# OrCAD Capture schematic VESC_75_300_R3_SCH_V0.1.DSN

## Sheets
1 01_Overview
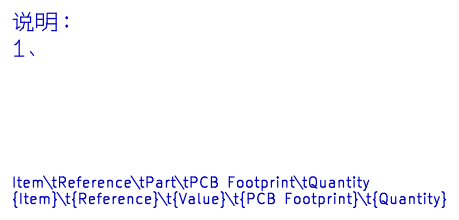
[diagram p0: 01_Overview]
2 02_Vresion
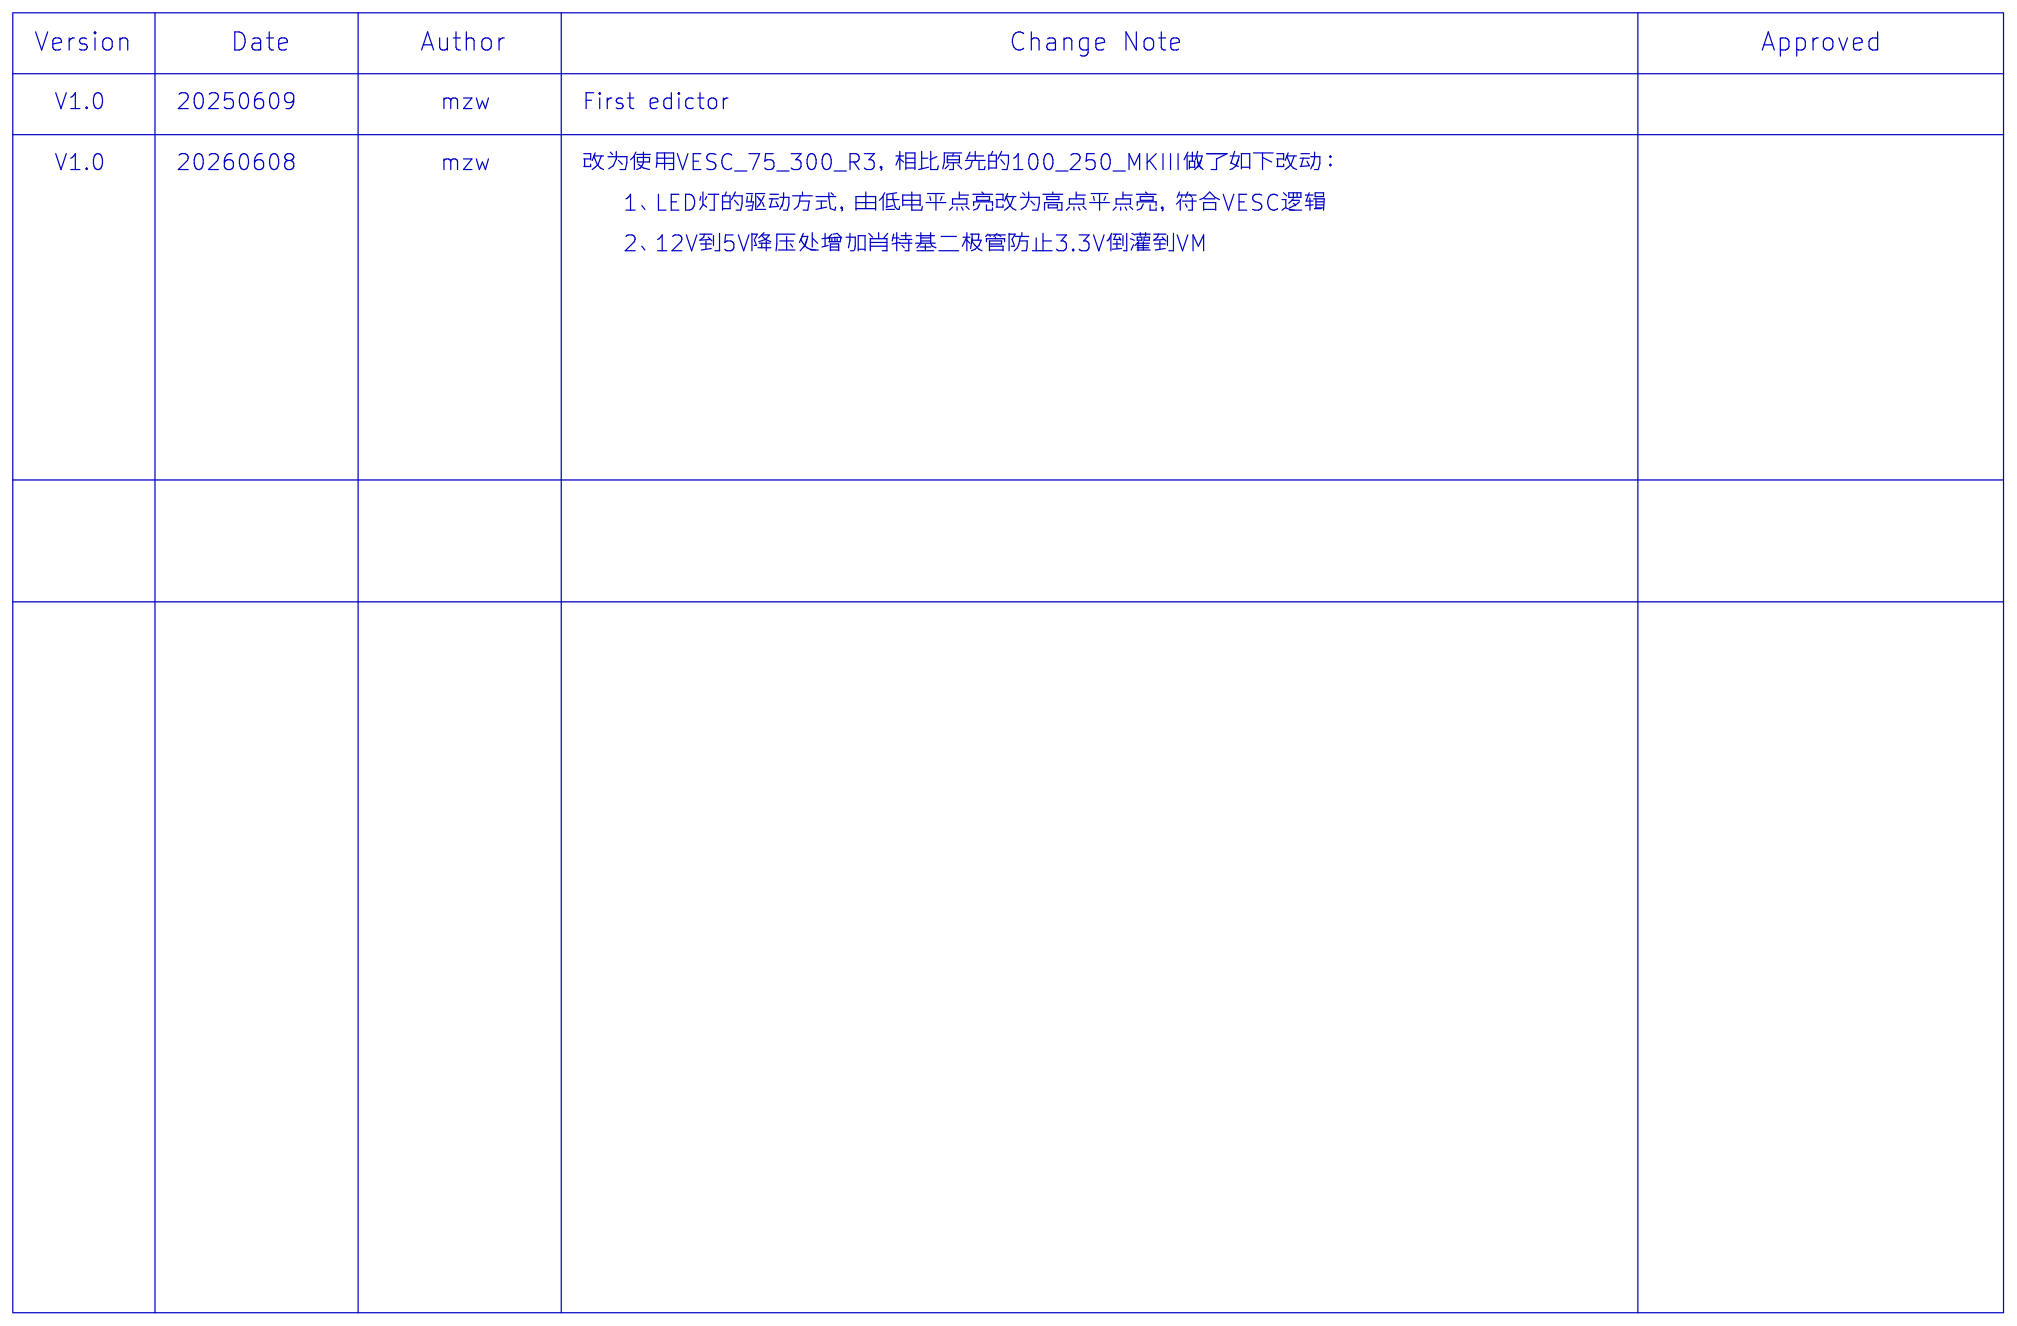
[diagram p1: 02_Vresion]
3 03_CAN: size A3
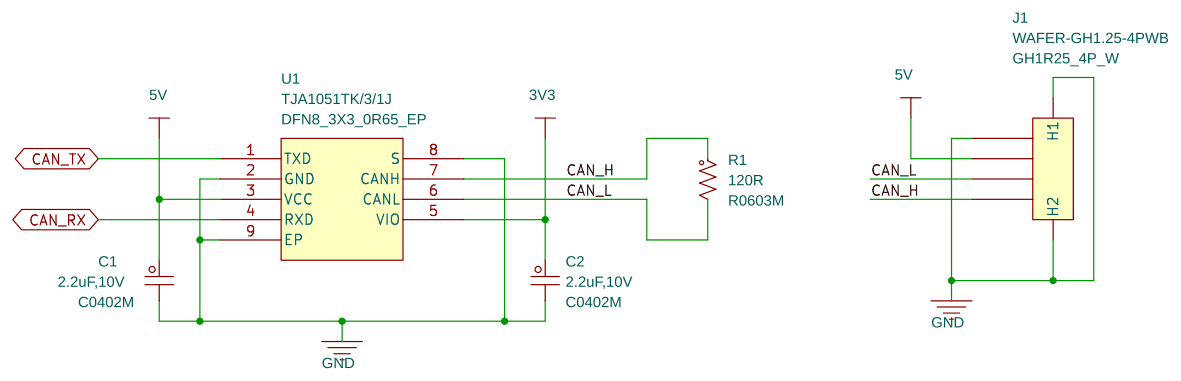
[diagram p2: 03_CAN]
4 04_MCU: size A3
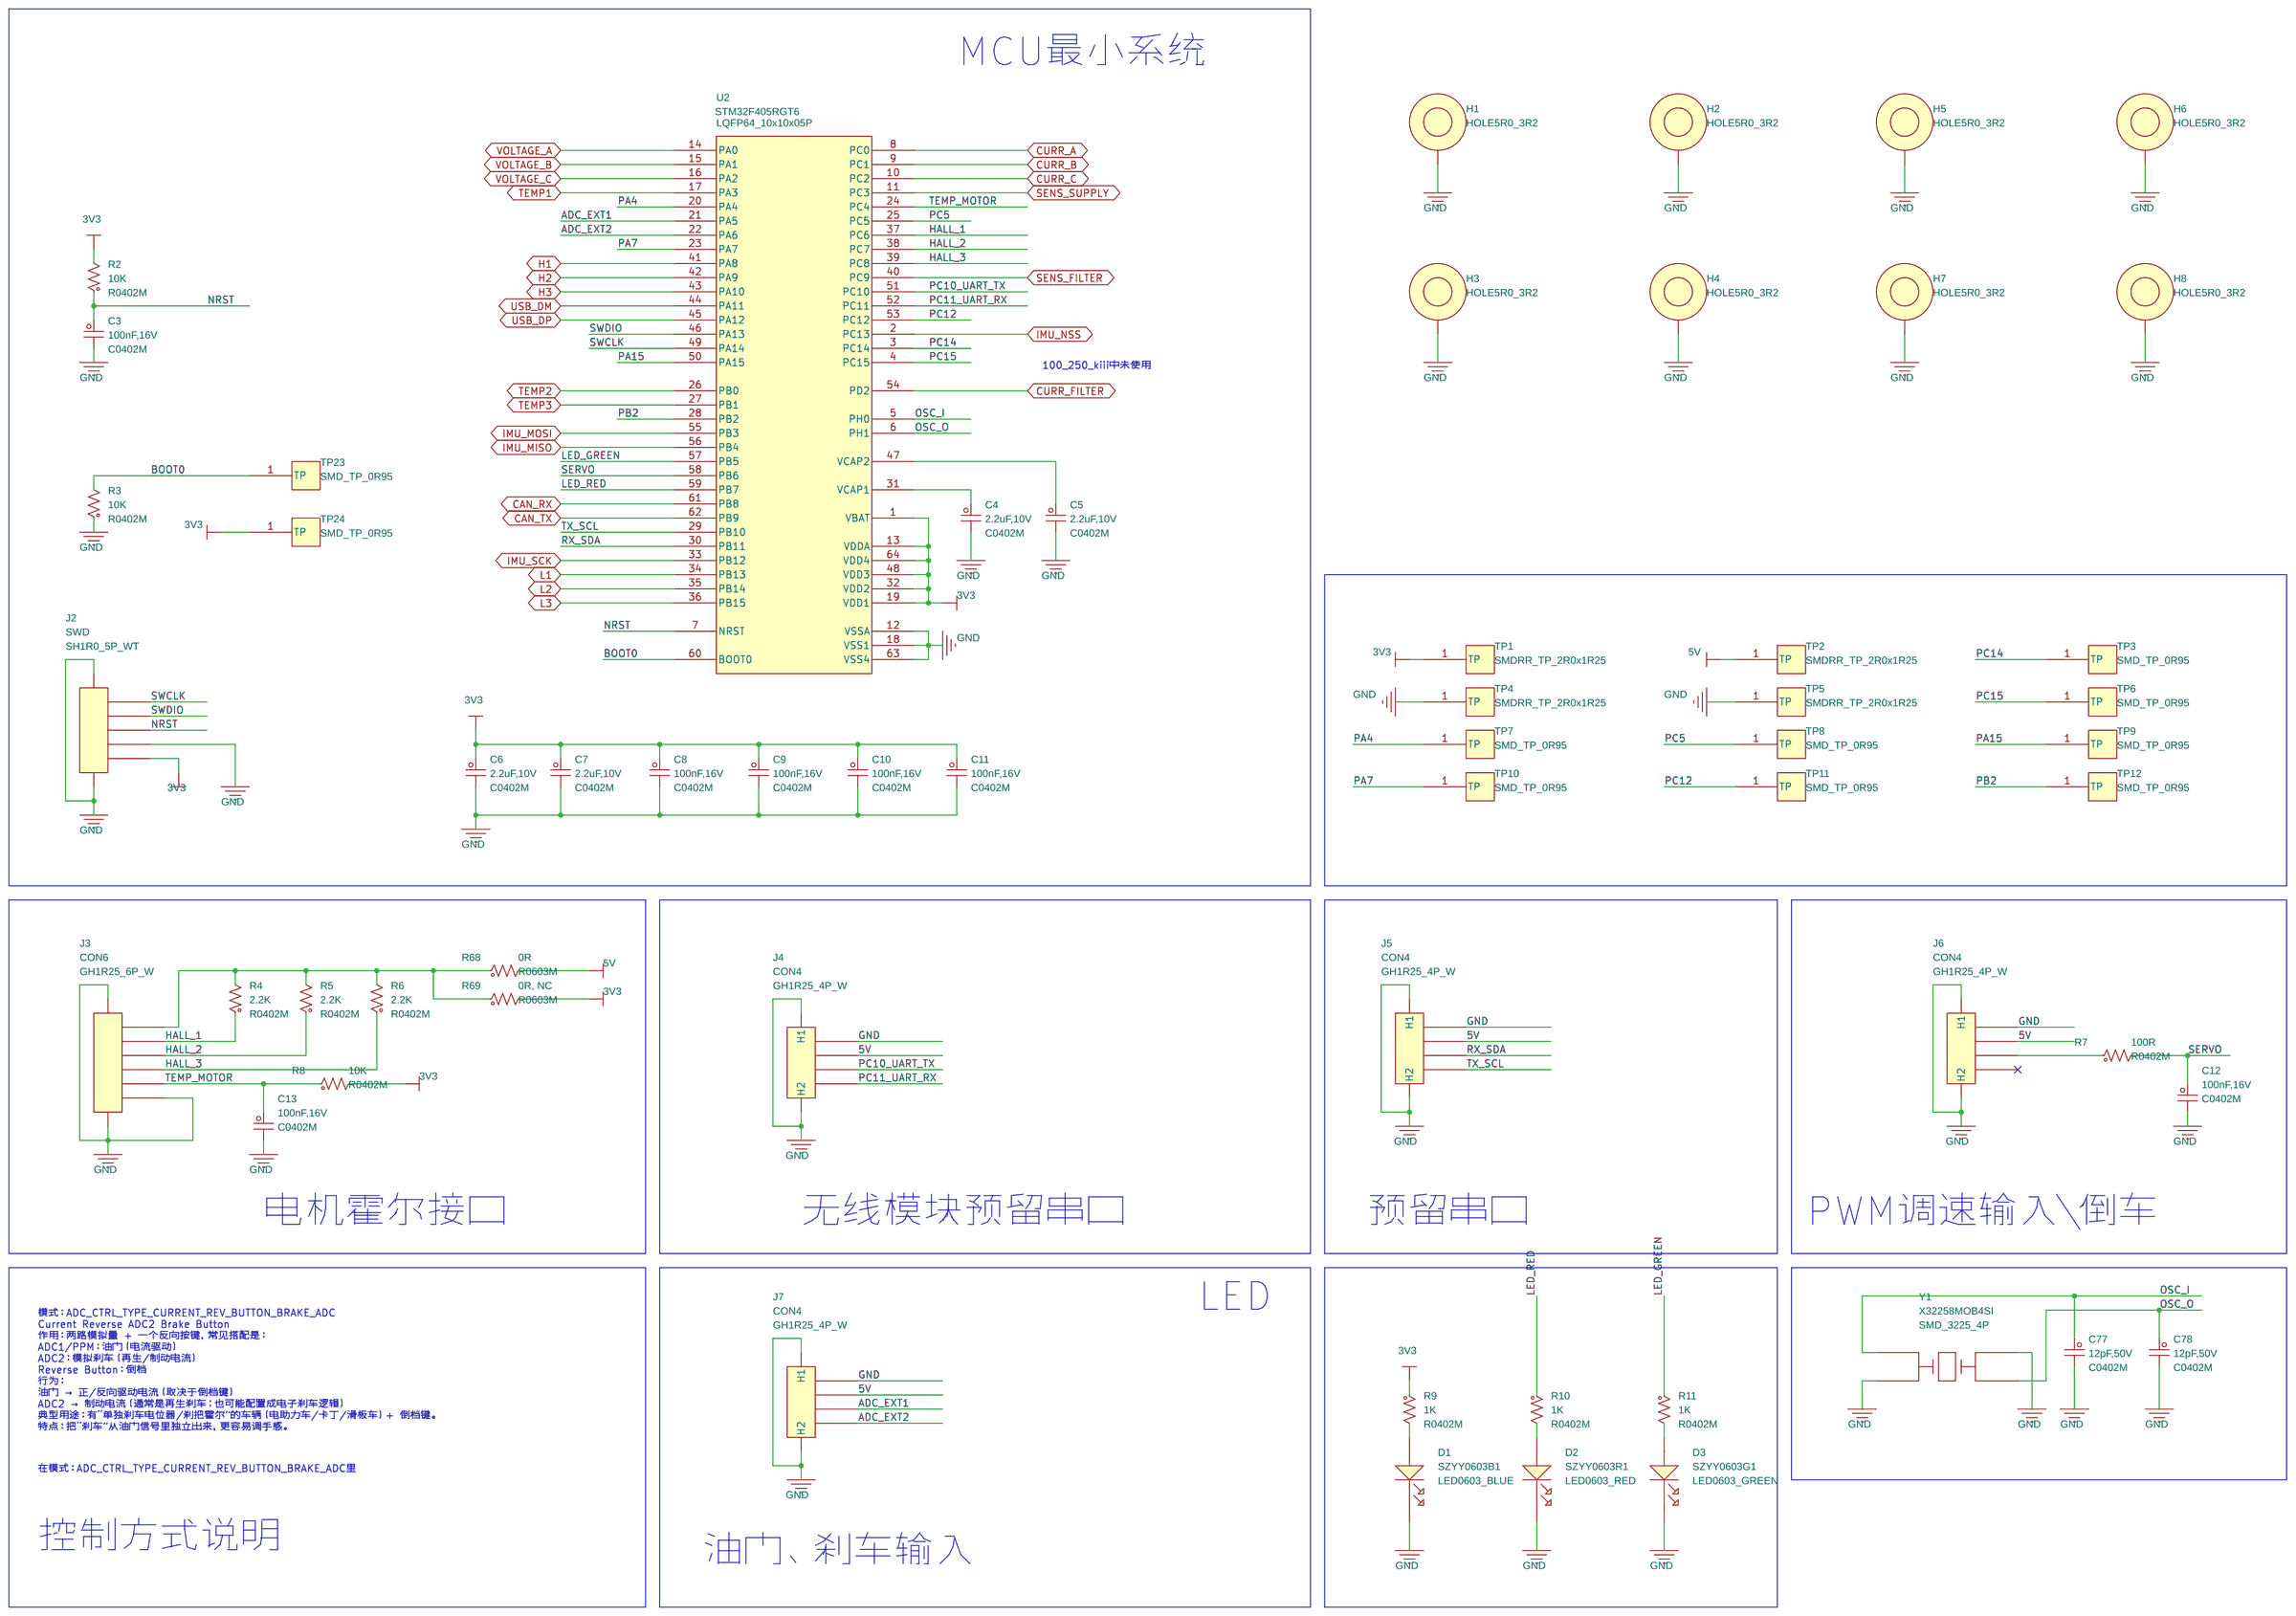
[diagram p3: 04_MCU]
5 05_Sensor: size A3
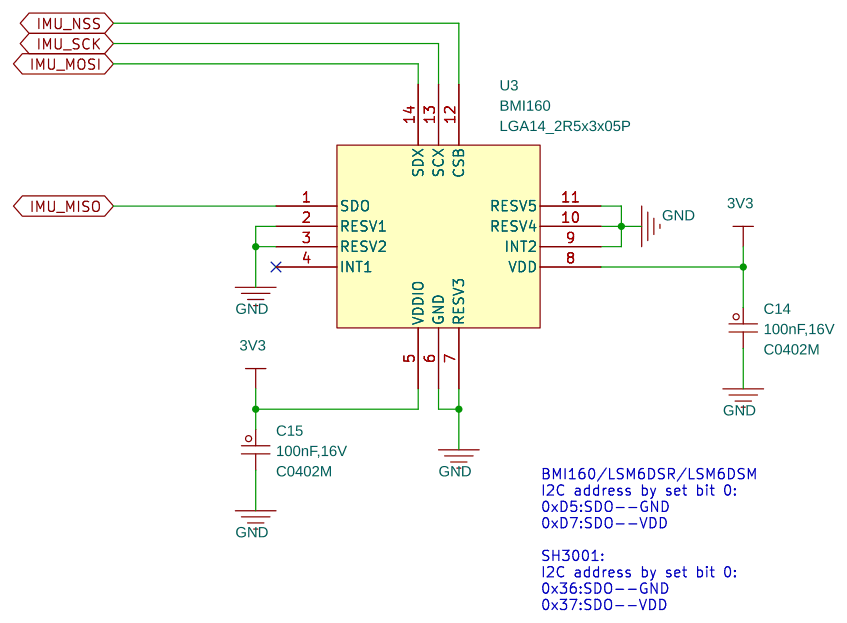
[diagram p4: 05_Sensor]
6 06_USB: size A3
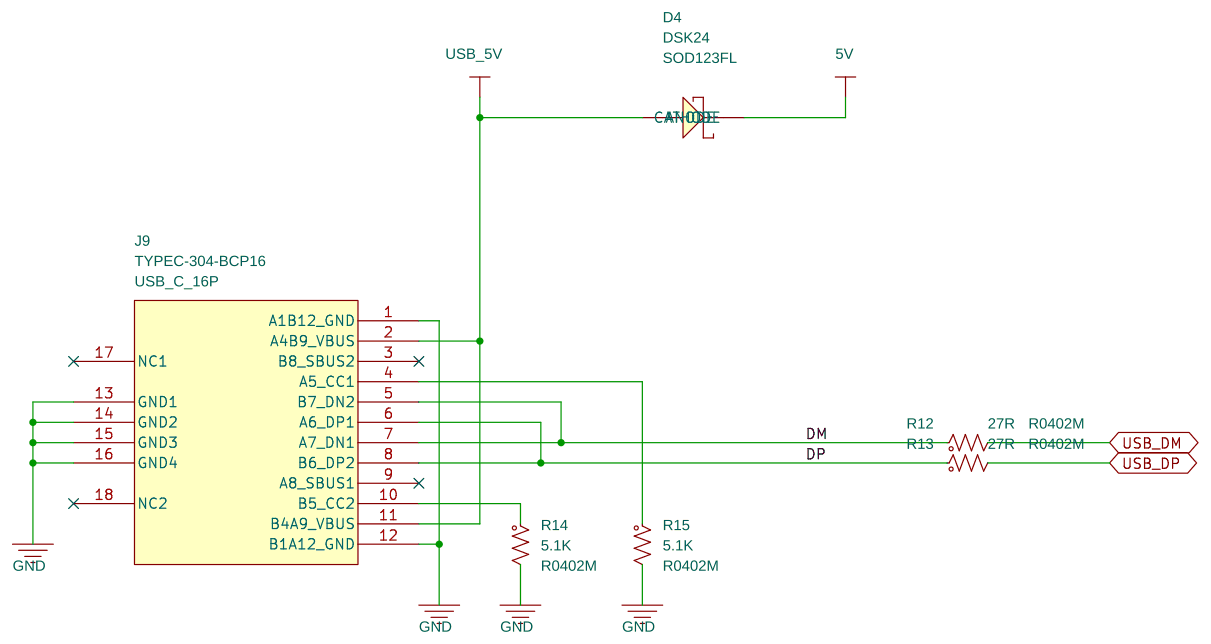
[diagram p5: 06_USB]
7 07_Power: size A3
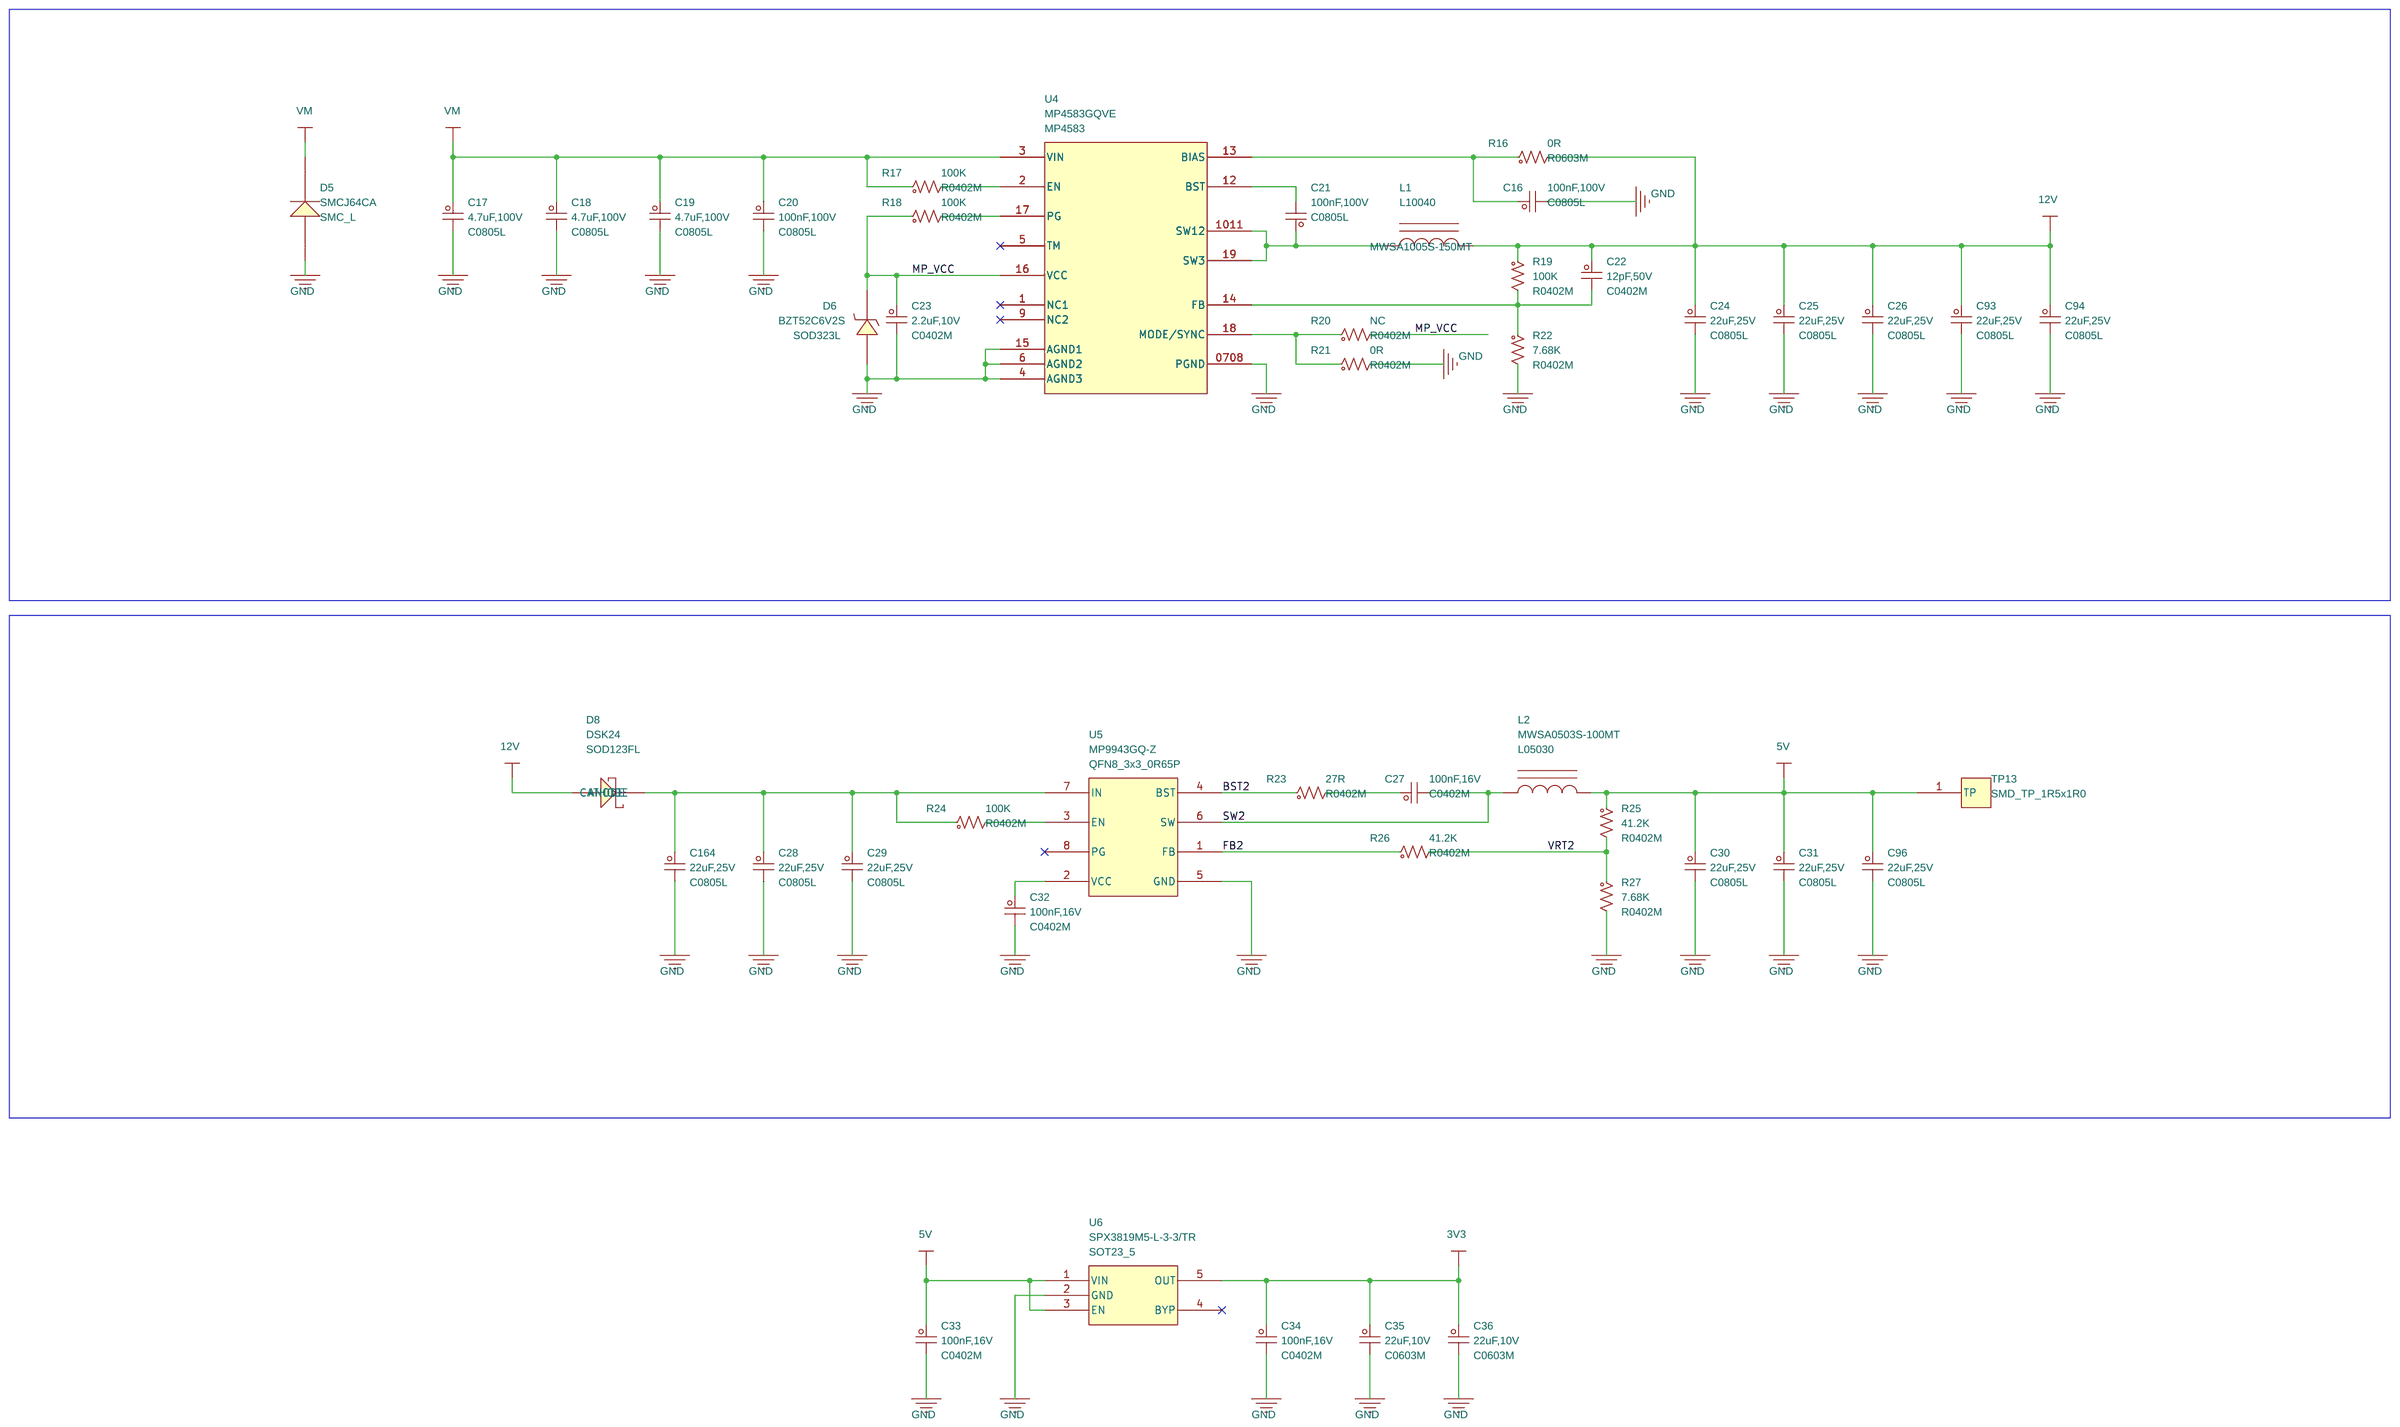
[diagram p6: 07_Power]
8 08_Motor: size A3
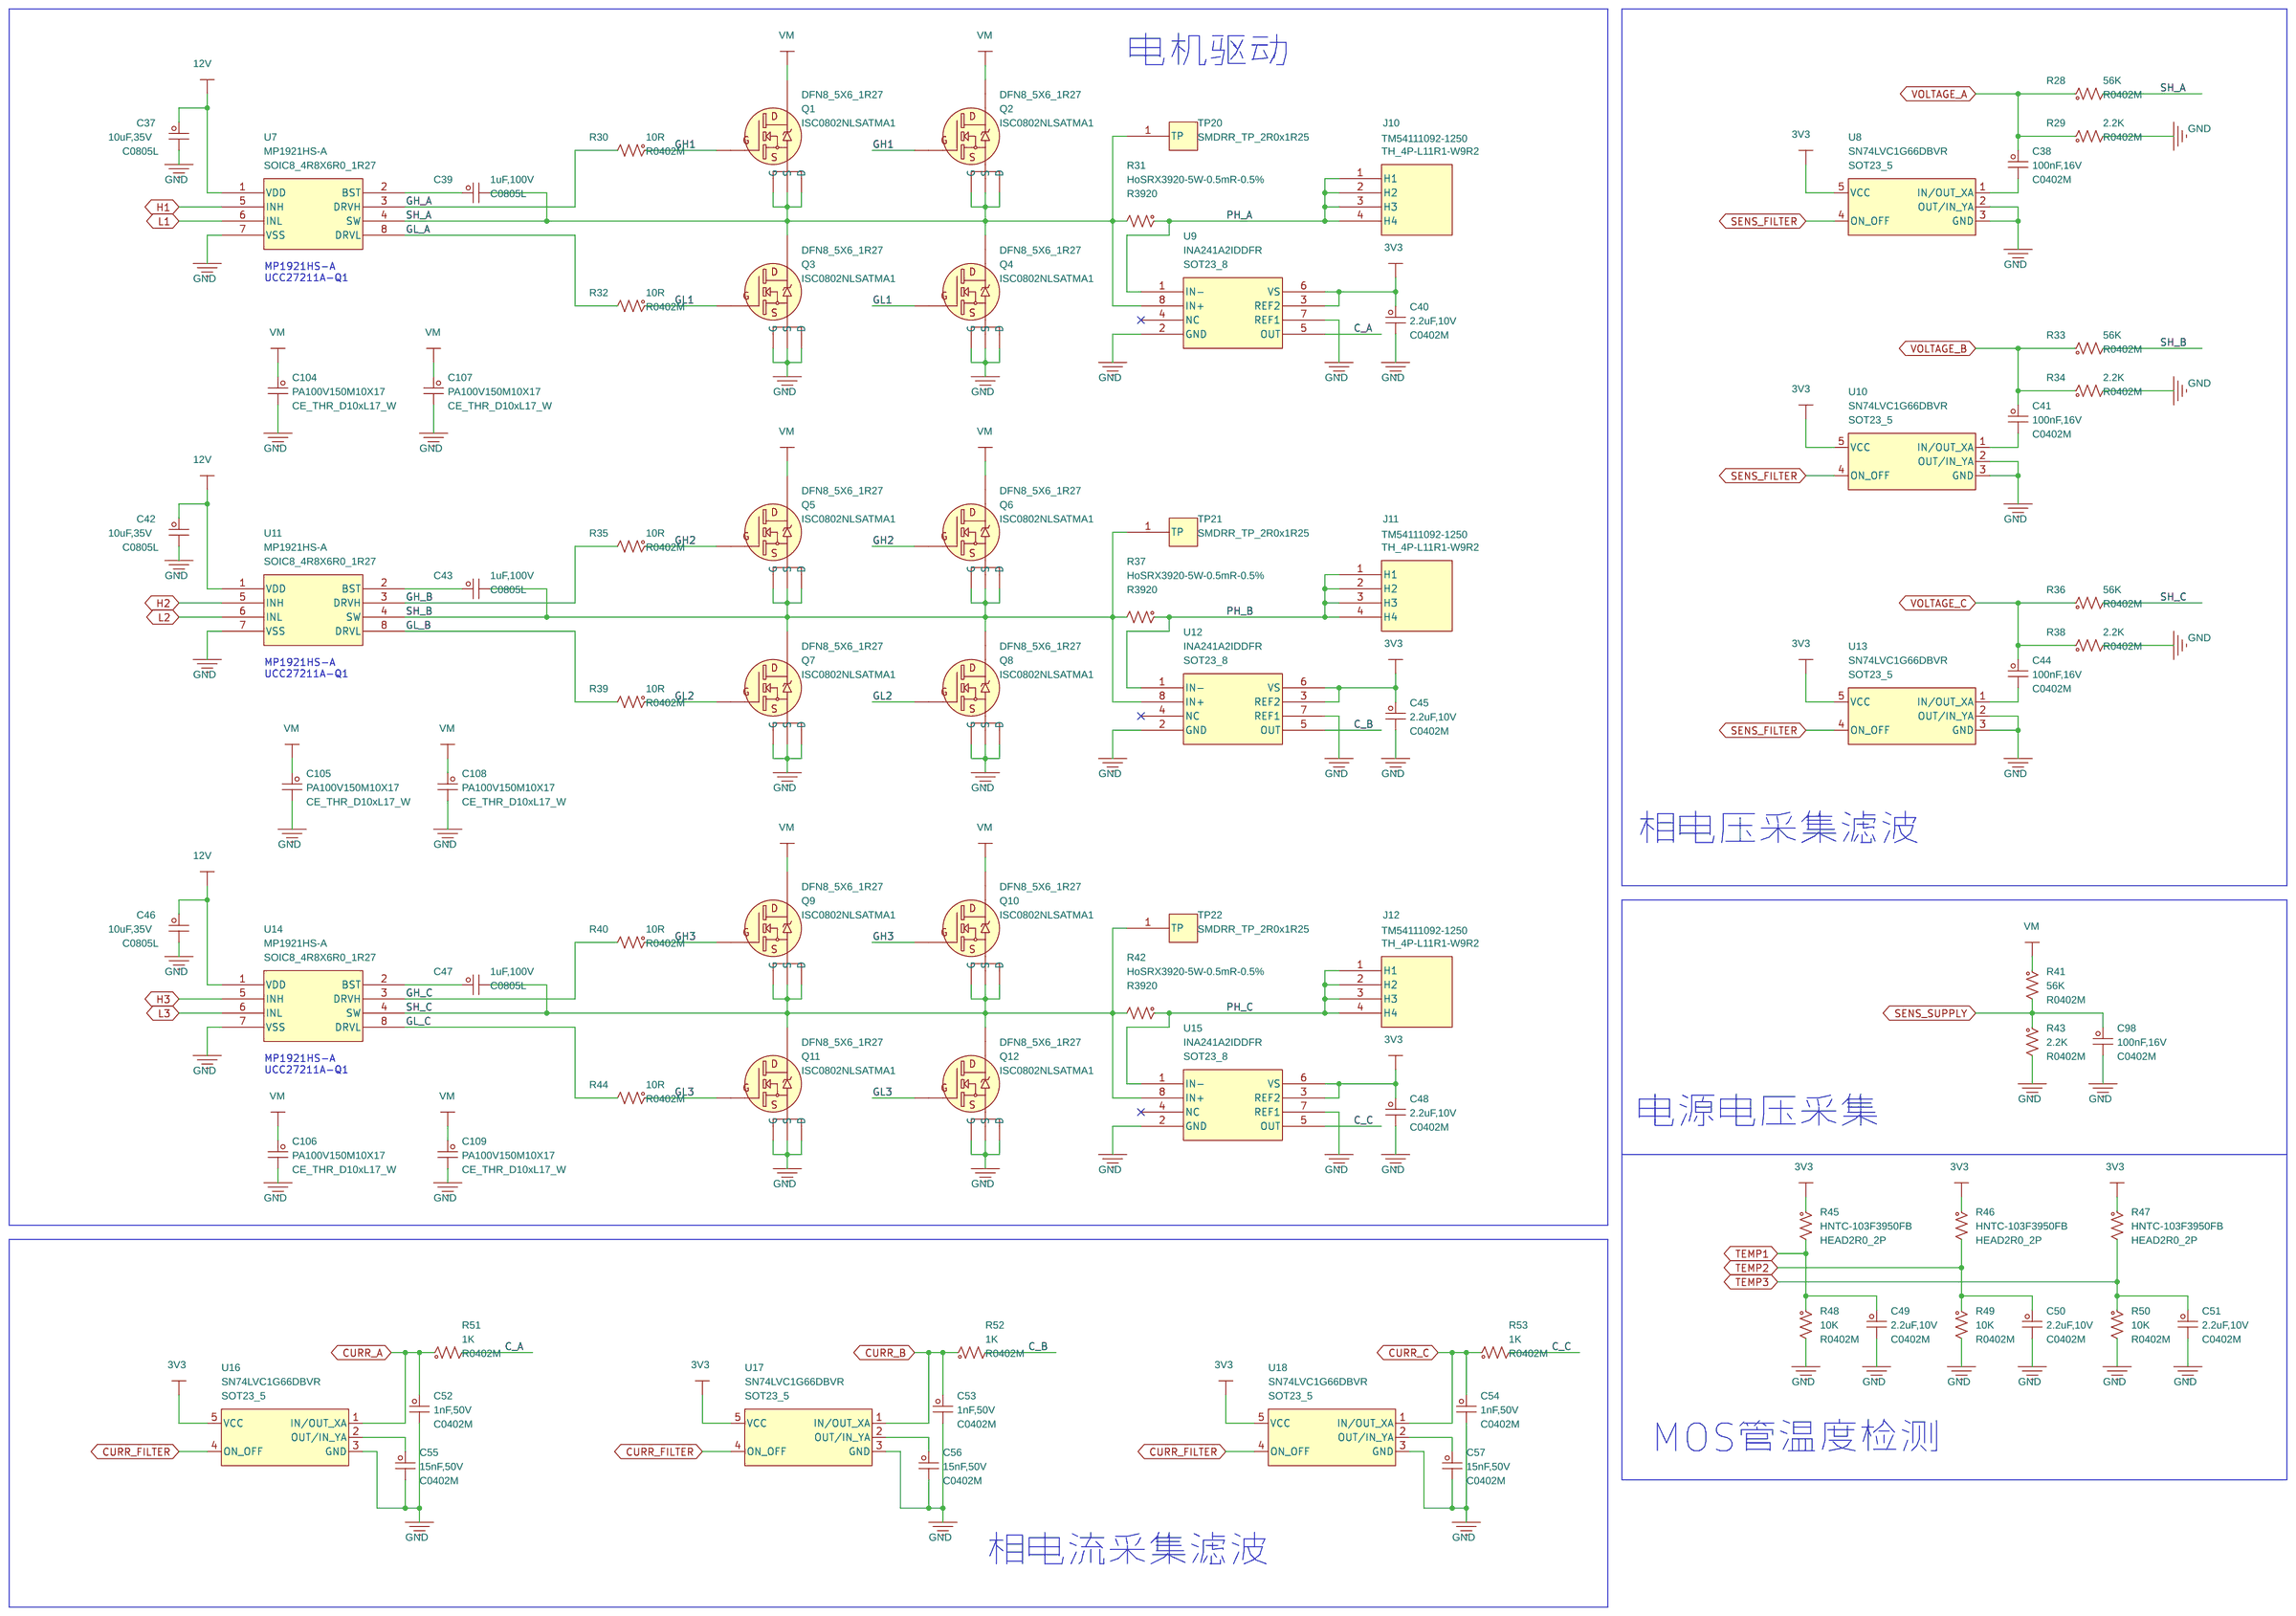
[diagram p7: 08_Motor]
9 09_eFuse: size A3
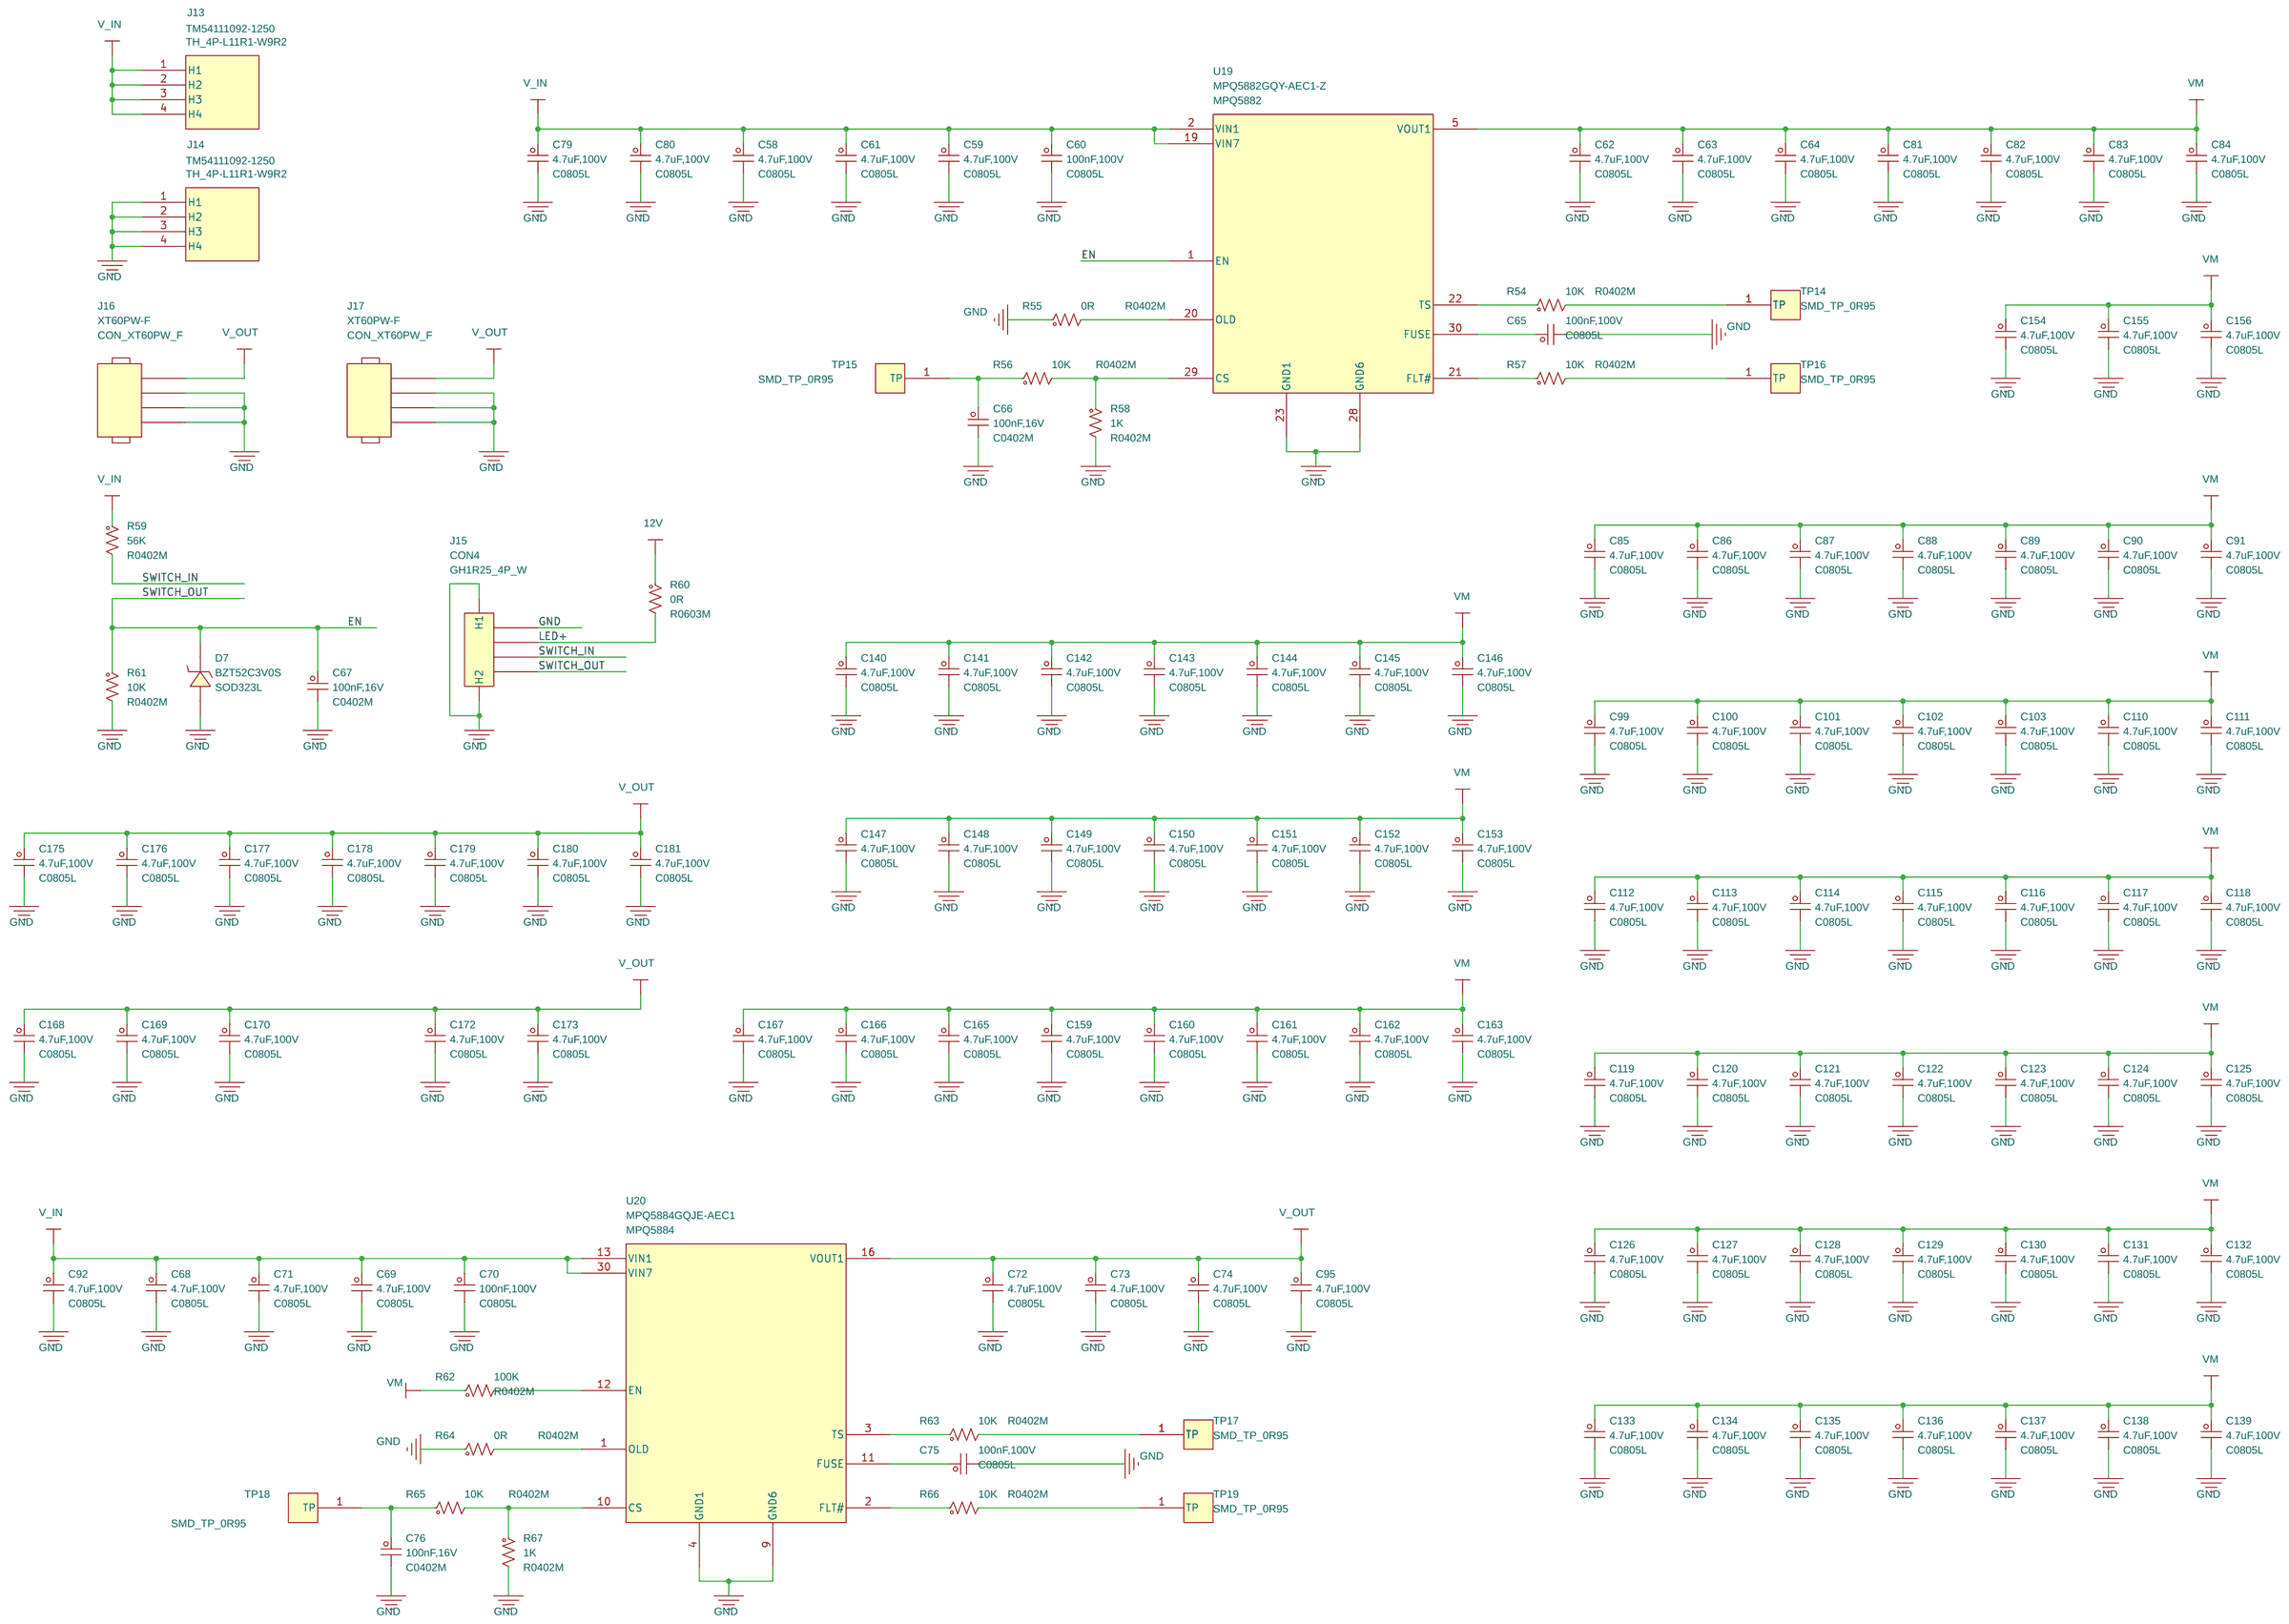
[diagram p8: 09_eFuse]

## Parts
sheet 03_CAN
C1  2.2uF,10V  [C0402M]
C2  2.2uF,10V  [C0402M]
J1  WAFER-GH1.25-4PWB  [GH1R25_4P_W]
R1  120R  [R0603M]
U1  TJA1051TK/3/1J  [DFN8_3X3_0R65_EP]
sheet 04_MCU
C3  100nF,16V  [C0402M]
C4  2.2uF,10V  [C0402M]
C5  2.2uF,10V  [C0402M]
C6  2.2uF,10V  [C0402M]
C7  2.2uF,10V  [C0402M]
C8  100nF,16V  [C0402M]
C9  100nF,16V  [C0402M]
C10  100nF,16V  [C0402M]
C11  100nF,16V  [C0402M]
C12  100nF,16V  [C0402M]
C13  100nF,16V  [C0402M]
C77  12pF,50V  [C0402M]
C78  12pF,50V  [C0402M]
D1  SZYY0603B1  [LED0603_BLUE]
D2  SZYY0603R1  [LED0603_RED]
D3  SZYY0603G1  [LED0603_GREEN]
H1  HOLE  [HOLE5R0_3R2]
H2  HOLE  [HOLE5R0_3R2]
H3  HOLE  [HOLE5R0_3R2]
H4  HOLE  [HOLE5R0_3R2]
H5  HOLE  [HOLE5R0_3R2]
H6  HOLE  [HOLE5R0_3R2]
H7  HOLE  [HOLE5R0_3R2]
H8  HOLE  [HOLE5R0_3R2]
J2  SWD  [SH1R0_5P_WT]
J3  CON6  [GH1R25_6P_W]
J4  CON4  [GH1R25_4P_W]
J5  CON4  [GH1R25_4P_W]
J6  CON4  [GH1R25_4P_W]
J7  CON4  [GH1R25_4P_W]
R2  10K  [R0402M]
R3  10K  [R0402M]
R4  2.2K  [R0402M]
R5  2.2K  [R0402M]
R6  2.2K  [R0402M]
R7  100R  [R0402M]
R8  10K  [R0402M]
R9  1K  [R0402M]
R10  1K  [R0402M]
R11  1K  [R0402M]
R68  0R  [R0603M]
R69  0R, NC  [R0603M]
TP1  TestPoint  [SMDRR_TP_2R0x1R25]
TP2  TestPoint  [SMDRR_TP_2R0x1R25]
TP3  TestPoint  [SMD_TP_0R95]
TP4  TestPoint  [SMDRR_TP_2R0x1R25]
TP5  TestPoint  [SMDRR_TP_2R0x1R25]
TP6  TestPoint  [SMD_TP_0R95]
TP7  TestPoint  [SMD_TP_0R95]
TP8  TestPoint  [SMD_TP_0R95]
TP9  TestPoint  [SMD_TP_0R95]
TP10  TestPoint  [SMD_TP_0R95]
TP11  TestPoint  [SMD_TP_0R95]
TP12  TestPoint  [SMD_TP_0R95]
TP23  TestPoint  [SMD_TP_0R95]
TP24  TestPoint  [SMD_TP_0R95]
U2  STM32F405RGT6  [LQFP64_10x10x05P]
Y1  X32258MOB4SI  [SMD_3225_4P]
sheet 05_Sensor
C14  100nF,16V  [C0402M]
C15  100nF,16V  [C0402M]
U3  BMI160  [LGA14_2R5x3x05P]
sheet 06_USB
D4  DSK24  [SOD123FL]
J9  TYPEC-304-BCP16  [USB_C_16P]
R12  27R  [R0402M]
R13  27R  [R0402M]
R14  5.1K  [R0402M]
R15  5.1K  [R0402M]
sheet 07_Power
C16  100nF,100V  [C0805L]
C17  4.7uF,100V  [C0805L]
C18  4.7uF,100V  [C0805L]
C19  4.7uF,100V  [C0805L]
C20  100nF,100V  [C0805L]
C21  100nF,100V  [C0805L]
C22  12pF,50V  [C0402M]
C23  2.2uF,10V  [C0402M]
C24  22uF,25V  [C0805L]
C25  22uF,25V  [C0805L]
C26  22uF,25V  [C0805L]
C27  100nF,16V  [C0402M]
C28  22uF,25V  [C0805L]
C29  22uF,25V  [C0805L]
C30  22uF,25V  [C0805L]
C31  22uF,25V  [C0805L]
C32  100nF,16V  [C0402M]
C33  100nF,16V  [C0402M]
C34  100nF,16V  [C0402M]
C35  22uF,10V  [C0603M]
C36  22uF,10V  [C0603M]
C93  22uF,25V  [C0805L]
C94  22uF,25V  [C0805L]
C96  22uF,25V  [C0805L]
C164  22uF,25V  [C0805L]
D5  SMCJ64CA  [SMC_L]
D6  BZT52C6V2S  [SOD323L]
D8  DSK24  [SOD123FL]
L1  MWSA1005S-150MT  [L10040]
L2  MWSA0503S-100MT  [L05030]
R16  0R  [R0603M]
R17  100K  [R0402M]
R18  100K  [R0402M]
R19  100K  [R0402M]
R20  NC  [R0402M]
R21  0R  [R0402M]
R22  7.68K  [R0402M]
R23  27R  [R0402M]
R24  100K  [R0402M]
R25  41.2K  [R0402M]
R26  41.2K  [R0402M]
R27  7.68K  [R0402M]
TP13  TestPoint  [SMD_TP_1R5x1R0]
U4  MP4583GQVE  [MP4583]
U5  MP9943GQ-Z  [QFN8_3x3_0R65P]
U6  SPX3819M5-L-3-3/TR  [SOT23_5]
sheet 08_Motor
C37  10uF,35V  [C0805L]
C38  100nF,16V  [C0402M]
C39  1uF,100V  [C0805L]
C40  2.2uF,10V  [C0402M]
C41  100nF,16V  [C0402M]
C42  10uF,35V  [C0805L]
C43  1uF,100V  [C0805L]
C44  100nF,16V  [C0402M]
C45  2.2uF,10V  [C0402M]
C46  10uF,35V  [C0805L]
C47  1uF,100V  [C0805L]
C48  2.2uF,10V  [C0402M]
C49  2.2uF,10V  [C0402M]
C50  2.2uF,10V  [C0402M]
C51  2.2uF,10V  [C0402M]
C52  1nF,50V  [C0402M]
C53  1nF,50V  [C0402M]
C54  1nF,50V  [C0402M]
C55  15nF,50V  [C0402M]
C56  15nF,50V  [C0402M]
C57  15nF,50V  [C0402M]
C98  100nF,16V  [C0402M]
C104  PA100V150M10X17  [CE_THR_D10xL17_W]
C105  PA100V150M10X17  [CE_THR_D10xL17_W]
C106  PA100V150M10X17  [CE_THR_D10xL17_W]
C107  PA100V150M10X17  [CE_THR_D10xL17_W]
C108  PA100V150M10X17  [CE_THR_D10xL17_W]
C109  PA100V150M10X17  [CE_THR_D10xL17_W]
J10  TM54111092-1250  [TH_4P-L11R1-W9R2]
J11  TM54111092-1250  [TH_4P-L11R1-W9R2]
J12  TM54111092-1250  [TH_4P-L11R1-W9R2]
Q1  ISC0802NLSATMA1  [DFN8_5X6_1R27]
Q2  ISC0802NLSATMA1  [DFN8_5X6_1R27]
Q3  ISC0802NLSATMA1  [DFN8_5X6_1R27]
Q4  ISC0802NLSATMA1  [DFN8_5X6_1R27]
Q5  ISC0802NLSATMA1  [DFN8_5X6_1R27]
Q6  ISC0802NLSATMA1  [DFN8_5X6_1R27]
Q7  ISC0802NLSATMA1  [DFN8_5X6_1R27]
Q8  ISC0802NLSATMA1  [DFN8_5X6_1R27]
Q9  ISC0802NLSATMA1  [DFN8_5X6_1R27]
Q10  ISC0802NLSATMA1  [DFN8_5X6_1R27]
Q11  ISC0802NLSATMA1  [DFN8_5X6_1R27]
Q12  ISC0802NLSATMA1  [DFN8_5X6_1R27]
R28  56K  [R0402M]
R29  2.2K  [R0402M]
R30  10R  [R0402M]
R31  HoSRX3920-5W-0.5mR-0.5%  [R3920]
R32  10R  [R0402M]
R33  56K  [R0402M]
R34  2.2K  [R0402M]
R35  10R  [R0402M]
R36  56K  [R0402M]
R37  HoSRX3920-5W-0.5mR-0.5%  [R3920]
R38  2.2K  [R0402M]
R39  10R  [R0402M]
R40  10R  [R0402M]
R41  56K  [R0402M]
R42  HoSRX3920-5W-0.5mR-0.5%  [R3920]
R43  2.2K  [R0402M]
R44  10R  [R0402M]
R45  HNTC-103F3950FB  [HEAD2R0_2P]
R46  HNTC-103F3950FB  [HEAD2R0_2P]
R47  HNTC-103F3950FB  [HEAD2R0_2P]
R48  10K  [R0402M]
R49  10K  [R0402M]
R50  10K  [R0402M]
R51  1K  [R0402M]
R52  1K  [R0402M]
R53  1K  [R0402M]
TP20  TestPoint  [SMDRR_TP_2R0x1R25]
TP21  TestPoint  [SMDRR_TP_2R0x1R25]
TP22  TestPoint  [SMDRR_TP_2R0x1R25]
U7  MP1921HS-A  [SOIC8_4R8X6R0_1R27]
U8  SN74LVC1G66DBVR  [SOT23_5]
U9  INA241A2IDDFR  [SOT23_8]
U10  SN74LVC1G66DBVR  [SOT23_5]
U11  MP1921HS-A  [SOIC8_4R8X6R0_1R27]
U12  INA241A2IDDFR  [SOT23_8]
U13  SN74LVC1G66DBVR  [SOT23_5]
U14  MP1921HS-A  [SOIC8_4R8X6R0_1R27]
U15  INA241A2IDDFR  [SOT23_8]
U16  SN74LVC1G66DBVR  [SOT23_5]
U17  SN74LVC1G66DBVR  [SOT23_5]
U18  SN74LVC1G66DBVR  [SOT23_5]
sheet 09_eFuse
C58  4.7uF,100V  [C0805L]
C59  4.7uF,100V  [C0805L]
C60  100nF,100V  [C0805L]
C61  4.7uF,100V  [C0805L]
C62  4.7uF,100V  [C0805L]
C63  4.7uF,100V  [C0805L]
C64  4.7uF,100V  [C0805L]
C65  100nF,100V  [C0805L]
C66  100nF,16V  [C0402M]
C67  100nF,16V  [C0402M]
C68  4.7uF,100V  [C0805L]
C69  4.7uF,100V  [C0805L]
C70  100nF,100V  [C0805L]
C71  4.7uF,100V  [C0805L]
C72  4.7uF,100V  [C0805L]
C73  4.7uF,100V  [C0805L]
C74  4.7uF,100V  [C0805L]
C75  100nF,100V  [C0805L]
C76  100nF,16V  [C0402M]
C79  4.7uF,100V  [C0805L]
C80  4.7uF,100V  [C0805L]
C81  4.7uF,100V  [C0805L]
C82  4.7uF,100V  [C0805L]
C83  4.7uF,100V  [C0805L]
C84  4.7uF,100V  [C0805L]
C85  4.7uF,100V  [C0805L]
C86  4.7uF,100V  [C0805L]
C87  4.7uF,100V  [C0805L]
C88  4.7uF,100V  [C0805L]
C89  4.7uF,100V  [C0805L]
C90  4.7uF,100V  [C0805L]
C91  4.7uF,100V  [C0805L]
C92  4.7uF,100V  [C0805L]
C95  4.7uF,100V  [C0805L]
C99  4.7uF,100V  [C0805L]
C100  4.7uF,100V  [C0805L]
C101  4.7uF,100V  [C0805L]
C102  4.7uF,100V  [C0805L]
C103  4.7uF,100V  [C0805L]
C110  4.7uF,100V  [C0805L]
C111  4.7uF,100V  [C0805L]
C112  4.7uF,100V  [C0805L]
C113  4.7uF,100V  [C0805L]
C114  4.7uF,100V  [C0805L]
C115  4.7uF,100V  [C0805L]
C116  4.7uF,100V  [C0805L]
C117  4.7uF,100V  [C0805L]
C118  4.7uF,100V  [C0805L]
C119  4.7uF,100V  [C0805L]
C120  4.7uF,100V  [C0805L]
C121  4.7uF,100V  [C0805L]
C122  4.7uF,100V  [C0805L]
C123  4.7uF,100V  [C0805L]
C124  4.7uF,100V  [C0805L]
C125  4.7uF,100V  [C0805L]
C126  4.7uF,100V  [C0805L]
C127  4.7uF,100V  [C0805L]
C128  4.7uF,100V  [C0805L]
C129  4.7uF,100V  [C0805L]
C130  4.7uF,100V  [C0805L]
C131  4.7uF,100V  [C0805L]
C132  4.7uF,100V  [C0805L]
C133  4.7uF,100V  [C0805L]
C134  4.7uF,100V  [C0805L]
C135  4.7uF,100V  [C0805L]
C136  4.7uF,100V  [C0805L]
C137  4.7uF,100V  [C0805L]
C138  4.7uF,100V  [C0805L]
C139  4.7uF,100V  [C0805L]
C140  4.7uF,100V  [C0805L]
C141  4.7uF,100V  [C0805L]
C142  4.7uF,100V  [C0805L]
C143  4.7uF,100V  [C0805L]
C144  4.7uF,100V  [C0805L]
C145  4.7uF,100V  [C0805L]
C146  4.7uF,100V  [C0805L]
C147  4.7uF,100V  [C0805L]
C148  4.7uF,100V  [C0805L]
C149  4.7uF,100V  [C0805L]
C150  4.7uF,100V  [C0805L]
C151  4.7uF,100V  [C0805L]
C152  4.7uF,100V  [C0805L]
C153  4.7uF,100V  [C0805L]
C154  4.7uF,100V  [C0805L]
C155  4.7uF,100V  [C0805L]
C156  4.7uF,100V  [C0805L]
C159  4.7uF,100V  [C0805L]
C160  4.7uF,100V  [C0805L]
C161  4.7uF,100V  [C0805L]
C162  4.7uF,100V  [C0805L]
C163  4.7uF,100V  [C0805L]
C165  4.7uF,100V  [C0805L]
C166  4.7uF,100V  [C0805L]
C167  4.7uF,100V  [C0805L]
C168  4.7uF,100V  [C0805L]
C169  4.7uF,100V  [C0805L]
C170  4.7uF,100V  [C0805L]
C172  4.7uF,100V  [C0805L]
C173  4.7uF,100V  [C0805L]
C175  4.7uF,100V  [C0805L]
C176  4.7uF,100V  [C0805L]
C177  4.7uF,100V  [C0805L]
C178  4.7uF,100V  [C0805L]
C179  4.7uF,100V  [C0805L]
C180  4.7uF,100V  [C0805L]
C181  4.7uF,100V  [C0805L]
D7  BZT52C3V0S  [SOD323L]
J13  TM54111092-1250  [TH_4P-L11R1-W9R2]
J14  TM54111092-1250  [TH_4P-L11R1-W9R2]
J15  CON4  [GH1R25_4P_W]
J16  XT60PW-F  [CON_XT60PW_F]
J17  XT60PW-F  [CON_XT60PW_F]
R54  10K  [R0402M]
R55  0R  [R0402M]
R56  10K  [R0402M]
R57  10K  [R0402M]
R58  1K  [R0402M]
R59  56K  [R0402M]
R60  0R  [R0603M]
R61  10K  [R0402M]
R62  100K  [R0402M]
R63  10K  [R0402M]
R64  0R  [R0402M]
R65  10K  [R0402M]
R66  10K  [R0402M]
R67  1K  [R0402M]
TP14  TestPoint  [SMD_TP_0R95]
TP15  TestPoint  [SMD_TP_0R95]
TP16  TestPoint  [SMD_TP_0R95]
TP17  TestPoint  [SMD_TP_0R95]
TP18  TestPoint  [SMD_TP_0R95]
TP19  TestPoint  [SMD_TP_0R95]
U19  MPQ5882GQY-AEC1-Z  [MPQ5882]
U20  MPQ5884GQJE-AEC1  [MPQ5884]

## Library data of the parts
C1-C96 C98-C156 C159-C170 C172 C173 C175-C181 = Capacitor
J1 = CON4_0
R1-R69 = Resistor
U1 = TJA1051TK_3_1J_0
D1-D3 = LED_RED
H1-H8 = HOLE
J2 = CON5
J3 = CON6
J4-J7 J15 = CON4
TP1-TP24 = TestPoint
U2 = STM32F405RGT6
Y1 = CRYSTAL4_SM
U3 = ICM-42688-P
D4 D8 = DIODE_SCHOTTKY
J9 = USB_TYPE_C
D5 = BAS70_SOT_0
D6 D7 = BZT52C3V0S
L1 L2 = INDUCTOR_IRON
U4 = MP4583GQVE_4
U5 = MP9943GQ
U6 = SPX3819
J10-J14 = TM54111092-1250
Q1-Q12 = NMOS_2
U7 U11 U14 = MP1921HS-A_0
U8 U10 U13 U16-U18 = M74VHC1GT66DTT1G
U9 U12 U15 = INA241A2IDDFR_1
J16 J17 = HEADER_4
U19 = MPQ5882GQY-AEC1-Z_0
U20 = MPQ5884GQJE-AEC1_0

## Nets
3V3: C2.1 C6.1 C7.1 C8.1 C9.1 C10.1 C11.1 C14.1 C15.1 C34.1 C35.1 C36.1 C40.1 C45.1 C48.1 J2.5 R2.2 R8.2 R9.1 R45.1 R46.1 R47.1 R69.2 TP1.1(TP) TP24.1(TP) U1.5(VIO) U2.1(VBAT) U2.13(VDDA) U2.19(VDD1) U2.32(VDD2) U2.48(VDD3) U2.64(VDD4) U3.5(VDDIO) U3.8(VDD) U6.5(OUT) U8.5(VCC) U9.3(REF2) U9.6(VS) U10.5(VCC) U12.3(REF2) U12.6(VS) U13.5(VCC) U15.3(REF2) U15.6(VS) U16.5(VCC) U17.5(VCC) U18.5(VCC)
5V: C1.1 C30.1 C31.1 C33.1 C96.1 D4.2(CATHODE) J1.2 J4.2 J5.2 J6.2 J7.2 L2.2 R25.1 R68.2 TP2.1(TP) TP13.1(TP) U1.3(VCC) U6.1(VIN) U6.3(EN)
12V: C22.1 C24.1 C25.1 C26.1 C37.1 C42.1 C46.1 C93.1 C94.1 D8.1(ANODE) L1.2 R16.2 R19.1 R60.1 U7.1(VDD) U11.1(VDD) U14.1(VDD)
GND: C1.2 C2.2 C3.2 C4.2 C5.2 C6.2 C7.2 C8.2 C9.2 C10.2 C11.2 C12.2 C13.2 C14.2 C15.2 C16.2 C17.2 C18.2 C19.2 C20.2 C23.2 C24.2 C25.2 C26.2 C28.2 C29.2 C30.2 C31.2 C32.2 C33.2 C34.2 C35.2 C36.2 C37.2 C40.2 C42.2 C45.2 C46.2 C48.2 C49.2 C50.2 C51.2 C52.2 C53.2 C54.2 C55.2 C56.2 C57.2 C58.2 C59.2 C60.2 C61.2 C62.2 C63.2 C64.2 C65.2 C66.2 C67.2 C68.2 C69.2 C70.2 C71.2 C72.2 C73.2 C74.2 C75.2 C76.2 C77.2 C78.2 C79.2 C80.2 C81.2 C82.2 C83.2 C84.2 C85.2 C86.2 C87.2 C88.2 C89.2 C90.2 C91.2 C92.2 C93.2 C94.2 C95.2 C96.2 C98.2 C99.2 C100.2 C101.2 C102.2 C103.2 C104.2 C105.2 C106.2 C107.2 C108.2 C109.2 C110.2 C111.2 C112.2 C113.2 C114.2 C115.2 C116.2 C117.2 C118.2 C119.2 C120.2 C121.2 C122.2 C123.2 C124.2 C125.2 C126.2 C127.2 C128.2 C129.2 C130.2 C131.2 C132.2 C133.2 C134.2 C135.2 C136.2 C137.2 C138.2 C139.2 C140.2 C141.2 C142.2 C143.2 C144.2 C145.2 C146.2 C147.2 C148.2 C149.2 C150.2 C151.2 C152.2 C153.2 C154.2 C155.2 C156.2 C159.2 C160.2 C161.2 C162.2 C163.2 C164.2 C165.2 C166.2 C167.2 C168.2 C169.2 C170.2 C172.2 C173.2 C175.2 C176.2 C177.2 C178.2 C179.2 C180.2 C181.2 D1.2 D2.2 D3.2 D5.1(ANODE) D6.1(ANODE) D7.1(ANODE) H1.1 H2.1 H3.1 H4.1 H5.1 H6.1 H7.1 H8.1 J1.1 J1.5(H1) J1.6(H2) J2.4 J2.6 J2.7 J3.1 J3.7 J3.8 J4.1 J4.5(H1) J4.6(H2) J5.1 J5.5(H1) J5.6(H2) J6.1 J6.5(H1) J6.6(H2) J7.1 J7.5(H1) J7.6(H2) J9.1(A1B12_GND) J9.12(B1A12_GND) J9.13(GND1) J9.14(GND2) J9.15(GND3) J9.16(GND4) J14.1(H1) J14.2(H2) J14.3(H3) J14.4(H4) J15.1 J15.5(H1) J15.6(H2) J16.2 J16.3 J16.4 J17.2 J17.3 J17.4 Q3.1(G) Q3.2(S) Q3.3(D) Q4.1(G) Q4.2(S) Q4.3(D) Q7.1(G) Q7.2(S) Q7.3(D) Q8.1(G) Q8.2(S) Q8.3(D) Q11.1(G) Q11.2(S) Q11.3(D) Q12.1(G) Q12.2(S) Q12.3(D) R3.1 R14.2 R15.2 R21.2 R22.2 R27.2 R29.2 R34.2 R38.2 R43.2 R48.2 R49.2 R50.2 R55.1 R58.2 R61.2 R64.1 R67.2 TP4.1(TP) TP5.1(TP) U1.2(GND) U1.8(S) U1.9(EP) U2.12(VSSA) U2.18(VSS1) U2.63(VSS4) U3.2(RESV1) U3.3(RESV2) U3.6(GND) U3.7(RESV3) U3.9(INT2) U3.10(RESV4) U3.11(RESV5) U4.4(AGND3) U4.6(AGND2) U4.15(AGND1) U4.0708(PGND) U5.5(GND) U6.2(GND) U7.7(VSS) U8.2(OUT/IN_YA) U8.3(GND) U9.2(GND) U9.7(REF1) U10.2(OUT/IN_YA) U10.3(GND) U11.7(VSS) U12.2(GND) U12.7(REF1) U13.2(OUT/IN_YA) U13.3(GND) U14.7(VSS) U15.2(GND) U15.7(REF1) U16.3(GND) U17.3(GND) U18.3(GND) U19.23(GND1) U19.28(GND6) U20.4(GND1) U20.9(GND6) Y1.2 Y1.4
ADC_EXT1: J7.3 U2.21(PA5)
ADC_EXT2: J7.4 U2.22(PA6)
BOOT0: R3.2 TP23.1(TP) U2.60(BOOT0)
BST2: R23.1 U5.4(BST)
C_A: R51.2 U9.5(OUT)
C_B: R52.2 U12.5(OUT)
C_C: R53.2 U15.5(OUT)
CAN_H: J1.4 R1.1 U1.7(CANH)
CAN_L: J1.3 R1.2 U1.6(CANL)
CAN_RX: U1.4(RXD) U2.61(PB8)
CAN_TX: U1.1(TXD) U2.62(PB9)
CURR_A: C52.1 R51.1 U2.8(PC0) U16.1(IN/OUT_XA)
CURR_B: C53.1 R52.1 U2.9(PC1) U17.1(IN/OUT_XA)
CURR_C: C54.1 R53.1 U2.10(PC2) U18.1(IN/OUT_XA)
CURR_FILTER: U2.54(PD2) U16.4(ON_OFF) U17.4(ON_OFF) U18.4(ON_OFF)
DM: J9.5(B7_DN2) J9.7(A7_DN1) R12.1
DP: J9.6(A6_DP1) J9.8(B6_DP2) R13.1
EN: C67.1 D7.2(CATHODE) J15.4 R61.1 U19.1(EN)
FB2: R26.1 U5.1(FB)
GH1: Q1.4 Q2.4 R30.1
GH2: Q5.4 Q6.4 R35.1
GH3: Q9.4 Q10.4 R40.1
GH_A: R30.2 U7.3(DRVH)
GH_B: R35.2 U11.3(DRVH)
GH_C: R40.2 U14.3(DRVH)
GL1: Q3.4 Q4.4 R32.1
GL2: Q7.4 Q8.4 R39.1
GL3: Q11.4 Q12.4 R44.1
GL_A: R32.2 U7.8(DRVL)
GL_B: R39.2 U11.8(DRVL)
GL_C: R44.2 U14.8(DRVL)
H1: U2.41(PA8) U7.5(INH)
H2: U2.42(PA9) U11.5(INH)
H3: U2.43(PA10) U14.5(INH)
HALL_1: J3.5 R4.1 U2.37(PC6)
HALL_2: J3.4 R5.1 U2.38(PC7)
HALL_3: J3.3 R6.1 U2.39(PC8)
IMU_MISO: U2.56(PB4) U3.1(SDO)
IMU_MOSI: U2.55(PB3) U3.14(SDX)
IMU_NSS: U2.2(PC13) U3.12(CSB)
IMU_SCK: U2.33(PB12) U3.13(SCX)
L1: U2.34(PB13) U7.6(INL)
L2: U2.35(PB14) U11.6(INL)
L3: U2.36(PB15) U14.6(INL)
LED+: J15.2 R60.2
LED_GREEN: R11.1 U2.57(PB5)
LED_RED: R10.1 U2.59(PB7)
MP_VCC: C23.1 D6.2(CATHODE) R18.1 R20.2 U4.16(VCC)
NRST: C3.1 J2.3 R2.1 U2.7(NRST)
OSC_I: C77.1 U2.5(PH0) Y1.1
OSC_O: C78.1 U2.6(PH1) Y1.3
PA4: TP7.1(TP) U2.20(PA4)
PA7: TP10.1(TP) U2.23(PA7)
PA15: TP9.1(TP) U2.50(PA15)
PB2: TP12.1(TP) U2.28(PB2)
PC5: TP8.1(TP) U2.25(PC5)
PC10_UART_TX: J4.3 U2.51(PC10)
PC11_UART_RX: J4.4 U2.52(PC11)
PC12: TP11.1(TP) U2.53(PC12)
PC14: TP3.1(TP) U2.3(PC14)
PC15: TP6.1(TP) U2.4(PC15)
PH_A: J10.1(H1) J10.2(H2) J10.3(H3) J10.4(H4) R31.1 U9.1(IN-)
PH_B: J11.1(H1) J11.2(H2) J11.3(H3) J11.4(H4) R37.1 U12.1(IN-)
PH_C: J12.1(H1) J12.2(H2) J12.3(H3) J12.4(H4) R42.1 U15.1(IN-)
RX_SDA: J5.3 U2.30(PB11)
SENS_FILTER: U2.40(PC9) U8.4(ON_OFF) U10.4(ON_OFF) U13.4(ON_OFF)
SENS_SUPPLY: C98.1 R41.2 R43.1 U2.11(PC3)
SERVO: C12.1 R7.2 U2.58(PB6)
SH_A: C39.2 Q1.1(G) Q1.2(S) Q1.3(D) Q2.1(G) Q2.2(S) Q2.3(D) Q3.5 Q4.5 R28.2 R31.2 TP20.1(TP) U7.4(SW) U9.8(IN+)
SH_B: C43.2 Q5.1(G) Q5.2(S) Q5.3(D) Q6.1(G) Q6.2(S) Q6.3(D) Q7.5 Q8.5 R33.2 R37.2 TP21.1(TP) U11.4(SW) U12.8(IN+)
SH_C: C47.2 Q9.1(G) Q9.2(S) Q9.3(D) Q10.1(G) Q10.2(S) Q10.3(D) Q11.5 Q12.5 R36.2 R42.2 TP22.1(TP) U14.4(SW) U15.8(IN+)
SW2: C27.2 L2.1 U5.6(SW)
SWCLK: J2.1 U2.49(PA14)
SWDIO: J2.2 U2.46(PA13)
SWITCH_IN: J15.3 R59.2
TEMP1: C49.1 R45.2 R48.1 U2.17(PA3)
TEMP2: C50.1 R46.2 R49.1 U2.26(PB0)
TEMP3: C51.1 R47.2 R50.1 U2.27(PB1)
TEMP_MOTOR: C13.1 J3.2 R8.1 U2.24(PC4)
TX_SCL: J5.4 U2.29(PB10)
USB_5V: D4.1(ANODE) J9.2(A4B9_VBUS) J9.11(B4A9_VBUS)
USB_DM: R12.2 U2.44(PA11)
USB_DP: R13.2 U2.45(PA12)
V_IN: C58.1 C59.1 C60.1 C61.1 C68.1 C69.1 C70.1 C71.1 C79.1 C80.1 C92.1 J13.1(H1) J13.2(H2) J13.3(H3) J13.4(H4) R59.1 U19.2(VIN1) U19.19(VIN7) U20.13(VIN1) U20.30(VIN7)
V_OUT: C72.1 C73.1 C74.1 C95.1 C168.1 C169.1 C170.1 C172.1 C173.1 C175.1 C176.1 C177.1 C178.1 C179.1 C180.1 C181.1 J16.1 J17.1 U20.16(VOUT1)
VM: C17.1 C18.1 C19.1 C20.1 C62.1 C63.1 C64.1 C81.1 C82.1 C83.1 C84.1 C85.1 C86.1 C87.1 C88.1 C89.1 C90.1 C91.1 C99.1 C100.1 C101.1 C102.1 C103.1 C104.1 C105.1 C106.1 C107.1 C108.1 C109.1 C110.1 C111.1 C112.1 C113.1 C114.1 C115.1 C116.1 C117.1 C118.1 C119.1 C120.1 C121.1 C122.1 C123.1 C124.1 C125.1 C126.1 C127.1 C128.1 C129.1 C130.1 C131.1 C132.1 C133.1 C134.1 C135.1 C136.1 C137.1 C138.1 C139.1 C140.1 C141.1 C142.1 C143.1 C144.1 C145.1 C146.1 C147.1 C148.1 C149.1 C150.1 C151.1 C152.1 C153.1 C154.1 C155.1 C156.1 C159.1 C160.1 C161.1 C162.1 C163.1 C165.1 C166.1 C167.1 D5.2(CATHODE) Q1.5 Q2.5 Q5.5 Q6.5 Q9.5 Q10.5 R17.1 R41.1 R62.1 U4.3(VIN) U19.5(VOUT1)
VOLTAGE_A: C38.1 R28.1 R29.1 U2.14(PA0)
VOLTAGE_B: C41.1 R33.1 R34.1 U2.15(PA1)
VOLTAGE_C: C44.1 R36.1 R38.1 U2.16(PA2)
VRT2: R25.2 R26.2 R27.1
N16235463: J9.4(A5_CC1) R15.1
N16235501: J9.10(B5_CC2) R14.1
N16338047: C28.1 C29.1 C164.1 D8.2(CATHODE) R24.1 U5.7(IN)
N16338077: C27.1 R23.2
N16338173: R24.2 U5.3(EN)
N16338343: C32.1 U5.2(VCC)
N16391848: C4.1 U2.31(VCAP1)
N16392334: C5.1 U2.47(VCAP2)
N16473071: C55.1 U16.2(OUT/IN_YA)
N16474661: C56.1 U17.2(OUT/IN_YA)
N16475179: C57.1 U18.2(OUT/IN_YA)
N16482857: C39.1 U7.2(BST)
N16484022: C43.1 U11.2(BST)
N16484627: C47.1 U14.2(BST)
N16487013: C38.2 U8.1(IN/OUT_XA)
N16490840: C41.2 U10.1(IN/OUT_XA)
N16491435: C44.2 U13.1(IN/OUT_XA)
N16496750: R17.2 U4.2(EN)
N16496852: R18.2 U4.17(PG)
N16499184: C21.2 U4.12(BST)
N16499214: C21.1 L1.1 U4.19(SW3) U4.1011(SW12)
N16499272: C22.2 R19.2 R22.1 U4.14(FB)
N16499854: R20.1 R21.1 U4.18(MODE/SYNC)
N16500835: C16.1 R16.1 U4.13(BIAS)
N16529102: J3.6 R4.2 R5.2 R6.2 R68.1 R69.1
N16538043: J6.3 R7.1
N16545078: D1.1 R9.2
N16545082: D2.1 R10.2
N16545086: D3.1 R11.2
N16552333: R64.2 U20.1(OLD)
N16552454: R65.2 R67.1 U20.10(CS)
N16553313: C76.1 R65.1 TP18.1(TP)
N16553880: R63.1 U20.3(TS)
N16553884: R63.2 TP17.1(TP)
N16554375: R66.1 U20.2(FLT#)
N16554379: R66.2 TP19.1(TP)
N16554424: C75.1 U20.11(FUSE)
N16555248: R62.2 U20.12(EN)
N16566545: R54.1 U19.22(TS)
N16566549: R54.2 TP14.1(TP)
N16566557: R55.2 U19.20(OLD)
N16566589: C65.1 U19.30(FUSE)
N16566673: C66.1 R56.1 TP15.1(TP)
N16566685: R56.2 R58.1 U19.29(CS)
N16566697: R57.1 U19.21(FLT#)
N16566701: R57.2 TP16.1(TP)

Not connected (* = marked no-connect by the designer): J6 4*; J9 3(B8_SBUS2)* 9(A8_SBUS1)* 17(NC1)* 18(NC2)*; U3 4(INT1)*; U4 1(NC1)* 5(TM)* 9(NC2)*; U5 8(PG)*; U6 4(BYP)*; U9 4(NC)*; U12 4(NC)*; U15 4(NC)*

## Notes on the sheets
sheet 1
- 说明：
  1、
- Item\tReference\tPart\tPCB Footprint\tQuantity
  {Item}\t{Reference}\t{Value}\t{PCB Footprint}\t{Quantity}
sheet 2
- Version
- Date
- Author
- Change Note
- Approved
- V1.0
- 20250609
- mzw
- First edictor
- V1.0
- 20260608
- mzw
- 改为使用VESC_75_300_R3，相比原先的100_250_MKIII做了如下改动：
- 1、LED灯的驱动方式，由低电平点亮改为高点平点亮，符合VESC逻辑
- 2、12V到5V降压处增加肖特基二极管防止3.3V倒灌到VM
sheet 4
- MCU最小系统
- 100_250_kiii中未使用
- 电机霍尔接口
- 无线模块预留串口
- 预留串口
- PWM调速输入\倒车
- LED
- 模式：ADC_CTRL_TYPE_CURRENT_REV_BUTTON_BRAKE_ADC
  Current Reverse ADC2 Brake Button
  作用：两路模拟量 + 一个反向按键，常见搭配是：
  ADC1/PPM：油门（电流驱动）
  ADC2：模拟刹车（再生/制动电流）
  Reverse Button：倒档
  行为：
  油门 → 正/反向驱动电流（取决于倒档键）
  ADC2 → 制动电流（通常是再生刹车；也可能配置成电子刹车逻辑）
  典型用途：有“单独刹车电位器/刹把霍尔”的车辆（电助力车/卡丁/滑板车）+ 倒档键。
  特点：把“刹车”从油门信号里独立出来，更容易调手感。
- 在模式：ADC_CTRL_TYPE_CURRENT_REV_BUTTON_BRAKE_ADC里
- 控制方式说明
- 油门、刹车输入
sheet 5
- BMI160/LSM6DSR/LSM6DSM
  I2C address by set bit 0:
  0xD5:SDO--GND
  0xD7:SDO--VDD
  SH3001:
  I2C address by set bit 0:
  0x36:SDO--GND
  0x37:SDO--VDD
sheet 8
- 电机驱动
- MP1921HS-A
  UCC27211A-Q1
- MP1921HS-A
  UCC27211A-Q1
- 相电压采集滤波
- MP1921HS-A
  UCC27211A-Q1
- 电源电压采集
- MOS管温度检测
- 相电流采集滤波
